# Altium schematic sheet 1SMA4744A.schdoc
size 127 x 101 mm
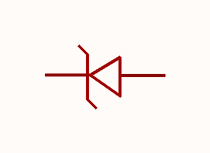
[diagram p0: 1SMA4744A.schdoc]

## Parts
D?  1sma4744a_c173484  [SMA_L4.4-W2.6-LS5.0-RD]  (value not drawn)

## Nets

Not connected (* = marked no-connect by the designer): D? 1(K) 2(A)

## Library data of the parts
D? = 1sma4744a_c173484: 二极管配置:1个独立式;稳压值(标称值):15V;稳压值(范围):13.8V~15.8V;耗散功率(Pd):1W;; Manufacturer: MDD(辰达半导体); AddInBom: yes; ModelId: a2d22152f8d5421c8e96dbd56af7c345; ModelTransform: 204.724,98.425,0,0,0,0,0,0,0; Diode Configuration: 1个独立式; Zener Voltage(Nom): 15V; Reverse Leakage Current (Ir): 5uA; Pd - Power Dissipation: 1W; Impedance(Zzt): 14Ω; Operating Junction Temperature Range: -55℃~+150℃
